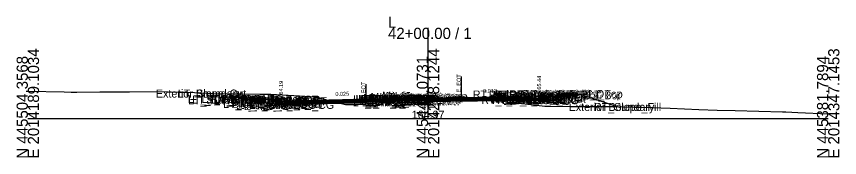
# Model space of a CAD drawing. Extents: x -26 to 4203, y -10 to 9526.
# Drawn here: x 2997.2 to 3202.8, y 1990.3 to 2025.4 of the extents above; entities that cross this region are included whole.
import ezdxf

# ---------------------------------------------------------------- set-up
doc = ezdxf.new("R2010")
doc.units = 0
for name, color, linetype in [('Default', 7, 'Continuous'), ('Exist CMT Pavement', 7, 'Continuous'), ('Exist Cross Section Cell', 7, 'Continuous'), ('Exist XS Center Line Elevation Label', 7, 'Continuous'), ('Exist XS Ground Line', 7, 'Continuous'), ('Prop CMT Conc Surface', 7, 'Continuous'), ('Prop CMT Concrete Structures', 7, 'Continuous'), ('Prop CMT Pvmt Course 1', 7, 'Continuous'), ('Prop CMT Pvmt Course 1 CG', 7, 'Continuous'), ('Prop CMT Pvmt Course 1 Wedge', 7, 'Continuous'), ('Prop CMT Pvmt Course 2', 7, 'Continuous'), ('Prop CMT Pvmt Course 2 Wedge', 7, 'Continuous'), ('Prop CMT Pvmt Course 3', 7, 'Continuous'), ('Prop CMT Pvmt Course 3 Wedge', 7, 'Continuous'), ('Prop CMT Pvmt Surface', 7, 'Continuous'), ('Prop CMT Pvmt Wedge Surface 1', 7, 'Continuous'), ('Prop CMT Pvmt Wedge Surface 2', 7, 'Continuous'), ('Prop CMT Pvmt Wedge Surface 3', 7, 'Continuous'), ('Prop CMT Slope Grass', 7, 'Continuous'), ('Prop CMT Subgrade Earthwork', 7, 'Continuous'), ('Prop XS Hydro Elevations', 7, 'Continuous'), ('Prop XS Label Text', 7, 'Continuous'), ('Prop XS SE Text', 7, 'Continuous'), ('Prop XS Side Slope Text', 7, 'Continuous'), ('Scratch_Level_0', 7, 'Continuous')]:
    doc.layers.add(name, color=color, linetype=linetype)

msp = doc.modelspace()

# ---------------------------------------------------------------- linework, layer by layer
at = {"layer": 'Exist CMT Pavement'}
for p, q in [((3084.46, 2003.6), (3085.63, 2003.74)), ((3085.63, 2003.74), (3089.14, 2004.08)), ((3089.14, 2004.08), (3092.69, 2004.41)), ((3092.69, 2004.41), (3095.44, 2004.64)), ((3095.44, 2004.64), (3096.5, 2004.72)), ((3096.5, 2004.72), (3099, 2004.9))]:
    msp.add_line(p, q, dxfattribs=at)
at = {"layer": 'Exist Cross Section Cell'}
for p, q in [((3100, 2000), (3100, 2022.62)), ((3000, 2000), (3100, 2000)), ((3100, 2000), (3200, 2000))]:
    msp.add_line(p, q, dxfattribs=at)
at = {"layer": 'Exist XS Ground Line'}
msp.add_lwpolyline([(3000, 2006.85), (3009.05, 2006.65), (3010.84, 2006.59), (3012.24, 2006.59), (3017.97, 2006.67), (3025.37, 2006.69), (3032.23, 2006.75), (3037.55, 2006.58), (3039.36, 2006.54), (3041.69, 2006.46), (3046.48, 2006.26), (3050.21, 2006.19), (3053.61, 2006.18), (3058.01, 2006.07), (3060.74, 2006.06), (3065.05, 2005.8), (3072.07, 2005.42), (3074.35, 2004.79), (3079.36, 2003.49), (3082.03, 2003.51), (3084.46, 2003.6), (3084.8, 2003.64), (3085.16, 2003.68), (3085.63, 2003.74), (3086.24, 2003.79), (3088.57, 2004.02), (3089.14, 2004.08), (3091.01, 2004.25), (3092.69, 2004.41), (3095.44, 2004.64), (3096.5, 2004.72), (3097.39, 2004.78), (3098.56, 2004.86), (3100, 2004.97), (3100.8, 2005.03), (3101.34, 2005.07), (3101.76, 2005.1), (3104.45, 2005.27), (3104.95, 2005.3), (3107.62, 2005.47), (3107.92, 2005.48), (3108.29, 2005.48), (3111.48, 2005.18), (3116.23, 2004.6), (3120.8, 2004.08), (3129.21, 2003.1), (3136.32, 2003.04), (3146.28, 2002.98), (3151.46, 2002.88), (3153.41, 2002.82), (3155.92, 2002.74), (3160.54, 2002.6), (3164.11, 2002.4), (3167.66, 2002.23), (3172.24, 2002.13), (3176.77, 2002.01), (3188.56, 2001.68), (3189.43, 2001.66), (3192.41, 2001.52), (3200, 2001.18)], dxfattribs=at)
at = {"layer": 'Prop CMT Conc Surface'}
for points in [[(3125.77, 2005.5), (3127.77, 2005.44)], [(3127.77, 2005.44), (3127.77, 2005.94), (3128.27, 2005.94)], [(3132.27, 2006.03), (3137.27, 2006.13)], [(3058.75, 2004.78), (3053.75, 2004.88)], [(3063.25, 2004.19), (3063.25, 2004.69), (3062.75, 2004.69)], [(3065.25, 2004.32), (3063.25, 2004.19)]]:
    msp.add_lwpolyline(points, dxfattribs=at)
at = {"layer": 'Prop CMT Concrete Structures'}
for points in [[(3099, 2005.18), (3098.99, 2005.35), (3098.24, 2005.6), (3095.5, 2005.65), (3092.76, 2005.41), (3092.01, 2005.16), (3092, 2004.99)], [(3125.77, 2005.5), (3127.77, 2005.44), (3127.77, 2005.94), (3128.27, 2005.94)], [(3128.27, 2005.94), (3128.27, 2004.94), (3125.77, 2004.91)], [(3125.77, 2004.91), (3125.77, 2005.5)], [(3137.27, 2006.13), (3132.27, 2006.03)], [(3132.27, 2006.03), (3132.27, 2005.7)], [(3132.27, 2005.7), (3137.27, 2005.8)], [(3137.27, 2005.8), (3137.27, 2006.13)], [(3053.75, 2004.55), (3053.75, 2004.88)], [(3053.75, 2004.88), (3058.75, 2004.78)], [(3058.75, 2004.45), (3053.75, 2004.55)], [(3058.75, 2004.78), (3058.75, 2004.45)], [(3065.25, 2004.32), (3063.25, 2004.19), (3063.25, 2004.69), (3062.75, 2004.69)], [(3062.75, 2004.69), (3062.75, 2003.68), (3065.25, 2003.74)], [(3065.25, 2003.74), (3065.25, 2004.32)], [(3092, 2004.99), (3099, 2005.18)]]:
    msp.add_lwpolyline(points, dxfattribs=at)
at = {"layer": 'Prop CMT Pvmt Course 1'}
for points in [[(3099, 2005.18), (3125.77, 2005.5)], [(3125.77, 2005.5), (3125.77, 2005.25)], [(3092, 2004.99), (3065.25, 2004.32)], [(3065.25, 2004.07), (3084.46, 2004.56)], [(3065.25, 2004.32), (3065.25, 2004.07)], [(3084.46, 2004.68), (3092, 2004.87)], [(3084.46, 2004.56), (3084.46, 2004.68)], [(3092, 2004.99), (3099, 2005.18)], [(3092, 2004.74), (3092, 2004.99)], [(3092, 2004.74), (3092, 2004.99)], [(3099, 2004.93), (3092, 2004.74)], [(3092, 2004.87), (3092, 2004.74), (3092, 2004.74)], [(3125.77, 2005.25), (3099, 2004.93)], [(3099, 2005.18), (3099, 2004.93)], [(3099, 2004.93), (3099, 2005.18)]]:
    msp.add_lwpolyline(points, dxfattribs=at)
msp.add_lwpolyline([(3099, 2004.93), (3099, 2005.06), (3099, 2005.06), (3099, 2004.93)], close=True, dxfattribs=at)
at = {"layer": 'Prop CMT Pvmt Course 1 CG'}
for points in [[(3065.25, 2003.74), (3062.25, 2003.67), (3061.91, 2003.32)], [(3061.91, 2003.32), (3065.25, 2003.41)], [(3065.25, 2003.41), (3065.25, 2003.74)], [(3125.77, 2004.91), (3128.77, 2004.95), (3129.1, 2004.62)], [(3125.77, 2004.58), (3125.77, 2004.91)], [(3129.1, 2004.62), (3125.77, 2004.58)]]:
    msp.add_lwpolyline(points, dxfattribs=at)
at = {"layer": 'Prop CMT Pvmt Course 1 Wedge'}
for points in [[(3084.46, 2004.68), (3084.8, 2004.69), (3085.16, 2004.7), (3085.52, 2004.71), (3085.63, 2004.71), (3086.24, 2004.72), (3088.57, 2004.78), (3089.14, 2004.8), (3091.01, 2004.84), (3092, 2004.87)], [(3092, 2004.74), (3091.01, 2004.72), (3089.14, 2004.67), (3088.57, 2004.66), (3086.24, 2004.6), (3085.63, 2004.58), (3085.52, 2004.58), (3085.16, 2004.57), (3084.8, 2004.56), (3084.46, 2004.56)], [(3084.46, 2004.56), (3084.46, 2004.68)], [(3092, 2004.87), (3092, 2004.74)]]:
    msp.add_lwpolyline(points, dxfattribs=at)
at = {"layer": 'Prop CMT Pvmt Course 2'}
for points in [[(3084.46, 2004.56), (3065.25, 2004.07)], [(3065.25, 2003.74), (3084.46, 2004.22)], [(3065.25, 2004.07), (3065.25, 2003.74)], [(3084.46, 2004.22), (3084.46, 2004.56)], [(3092, 2004.74), (3099, 2004.93)], [(3092, 2004.41), (3092, 2004.74)], [(3099, 2004.6), (3092, 2004.41)], [(3099, 2004.93), (3125.77, 2005.25)], [(3099, 2004.93), (3099, 2004.6)], [(3099, 2004.6), (3099, 2004.93)], [(3125.77, 2004.92), (3099, 2004.6)], [(3125.77, 2005.25), (3125.77, 2004.91)]]:
    msp.add_lwpolyline(points, dxfattribs=at)
at = {"layer": 'Prop CMT Pvmt Course 2 Wedge'}
for points in [[(3084.46, 2004.56), (3084.8, 2004.56), (3085.16, 2004.57), (3085.52, 2004.58), (3085.63, 2004.58), (3086.24, 2004.6), (3088.57, 2004.66), (3089.14, 2004.67), (3091.01, 2004.72), (3092, 2004.74)], [(3084.46, 2004.22), (3084.46, 2004.56)], [(3092, 2004.41), (3091.01, 2004.38), (3089.14, 2004.34), (3088.57, 2004.32), (3086.24, 2004.27), (3085.63, 2004.25), (3085.52, 2004.25), (3085.16, 2004.24), (3084.8, 2004.23), (3084.46, 2004.22)], [(3092, 2004.74), (3092, 2004.41)]]:
    msp.add_lwpolyline(points, dxfattribs=at)
at = {"layer": 'Prop CMT Pvmt Course 3'}
for points in [[(3084.46, 2004.22), (3065.25, 2003.74)], [(3065.25, 2003.74), (3065.25, 2003.41)], [(3084.46, 2003.89), (3084.46, 2004.22)], [(3092, 2004.41), (3099, 2004.6)], [(3099, 2004.6), (3125.77, 2004.92)], [(3099, 2004.6), (3099, 2004.26)], [(3099, 2004.26), (3099, 2004.6)], [(3125.77, 2004.58), (3099, 2004.26)], [(3125.77, 2004.91), (3125.77, 2004.58)]]:
    msp.add_lwpolyline(points, dxfattribs=at)
at = {"layer": 'Prop CMT Pvmt Course 3 Wedge'}
for points in [[(3084.46, 2004.22), (3084.8, 2004.23), (3085.16, 2004.24), (3085.52, 2004.25), (3085.63, 2004.25), (3086.24, 2004.27), (3088.57, 2004.32), (3089.14, 2004.34), (3091.01, 2004.39), (3092, 2004.41)], [(3092, 2004.34), (3091.01, 2004.25), (3089.14, 2004.08), (3088.57, 2004.02), (3086.24, 2003.79), (3085.63, 2003.74), (3085.52, 2003.72), (3085.16, 2003.68), (3084.8, 2003.64), (3084.46, 2003.6)], [(3084.46, 2003.6), (3084.46, 2004.22)], [(3092, 2004.41), (3092, 2004.34)]]:
    msp.add_lwpolyline(points, dxfattribs=at)
at = {"layer": 'Prop CMT Pvmt Surface'}
for points in [[(3099, 2005.18), (3125.77, 2005.5)], [(3092, 2004.99), (3065.25, 2004.32)], [(3092, 2004.99), (3099, 2005.18)]]:
    msp.add_lwpolyline(points, dxfattribs=at)
at = {"layer": 'Prop CMT Pvmt Wedge Surface 1'}
for points in [[(3084.46, 2004.56), (3065.25, 2004.07)], [(3065.25, 2004.07), (3065.25, 2004.32)], [(3092, 2004.87), (3084.46, 2004.68)], [(3084.46, 2004.68), (3084.46, 2004.56)], [(3092, 2004.99), (3092, 2004.74), (3092, 2004.74), (3092, 2004.87)]]:
    msp.add_lwpolyline(points, dxfattribs=at)
at = {"layer": 'Prop CMT Pvmt Wedge Surface 2'}
for points in [[(3092, 2004.74), (3065.25, 2004.07)], [(3065.25, 2004.07), (3065.25, 2004.32)], [(3092, 2004.99), (3092, 2004.74)]]:
    msp.add_lwpolyline(points, dxfattribs=at)
at = {"layer": 'Prop CMT Pvmt Wedge Surface 3'}
for points in [[(3092, 2004.41), (3065.25, 2003.74)], [(3065.25, 2003.74), (3065.25, 2004.32)], [(3092, 2004.99), (3092, 2004.41)]]:
    msp.add_lwpolyline(points, dxfattribs=at)
at = {"layer": 'Prop CMT Slope Grass'}
for points in [[(3062.75, 2004.69), (3053.25, 2004.88), (3049.28, 2006.21)], [(3128.27, 2005.94), (3137.27, 2006.12)], [(3137.27, 2006.12), (3137.77, 2006.13), (3147.24, 2002.98)]]:
    msp.add_lwpolyline(points, dxfattribs=at)
at = {"layer": 'Prop CMT Subgrade Earthwork'}
msp.add_line((3099, 2004.26), (3099, 2004.9), dxfattribs=at)
for points in [[(3125.77, 2004.58), (3129.1, 2004.62), (3130.46, 2005.99)], [(3065.25, 2003.41), (3061.91, 2003.32), (3060.49, 2004.74)], [(3084.46, 2003.89), (3065.25, 2003.41)], [(3084.46, 2003.89), (3084.48, 2003.6)], [(3099, 2004.26), (3125.77, 2004.58)]]:
    msp.add_lwpolyline(points, dxfattribs=at)
at = {"layer": 'Prop XS Label Text'}
for p, q in [((3108.29, 2010.48), (3108.29, 2005.48)), ((3084.46, 2008.6), (3084.46, 2003.6))]:
    msp.add_line(p, q, dxfattribs=at)

# ---------------------------------------------------------------- texts
at = {"layer": 'Default'}
msp.add_text('-', height=0.0001, dxfattribs=at).set_placement((3000, 2000))
at = {"layer": 'Exist Cross Section Cell'}
for s, p in [('L', (3090, 2022.62)), ('42+00.00 / 1', (3090, 2019.82))]:
    msp.add_text(s, height=2.8, dxfattribs=at).set_placement(p)
for s, p in [('E 2014189.1034', (3002.8, 1990)), ('E 2014268.1244', (3102.8, 1990)), ('E 2014347.1453', (3202.8, 1990)), ('N 445504.3568', (3000, 1990)), ('N 445443.0731', (3100, 1990)), ('N 445381.7894', (3200, 1990))]:
    msp.add_text(s, height=2.8, rotation=90, dxfattribs=at).set_placement(p)
at = {"layer": 'Exist XS Center Line Elevation Label'}
msp.add_text('164.97', height=2, dxfattribs=at).set_placement((3095.94, 1999.97))
at = {"layer": 'Prop XS Hydro Elevations'}
for s, p in [('165.44', (3128.27, 2006.44)), ('164.19', (3063.75, 2005.19))]:
    msp.add_text(s, height=1, rotation=90, dxfattribs=at).set_placement(p)
at = {"layer": 'Prop XS Label Text'}
for p in [(3108.19, 2006.5), (3084.36, 2004.62)]:
    msp.add_text('E. EOT', height=1, rotation=90, dxfattribs=at).set_placement(p)
at = {"layer": 'Prop XS SE Text'}
for s, rotation, p in [('0.025', 1.4327, (3076.87, 2005.61)), ('0.012', 0.6805, (3113.77, 2006.36))]:
    msp.add_text(s, height=1, rotation=rotation, dxfattribs=at).set_placement(p)
at = {"layer": 'Prop XS Side Slope Text'}
for p in [(3051.59, 2006.07), (3141.53, 2005.47)]:
    msp.add_text('3:1', height=1, rotation=341.5651, dxfattribs=at).set_placement(p)
at = {"layer": 'Scratch_Level_0'}
for s, p in [('Exterior Boundary', (3032, 2005.23)), ('LT_Slope_Cut', (3037.49, 2005.23)), ('LT_SDWK_Out_Top', (3039.99, 2003.89)), ('LT_SDWK_Out_Bot', (3040.02, 2003.55)), ('LT_Sub_Trench_Out_DLT', (3041.06, 2003.74)), ('LT_CSLP_Pnt', (3043.42, 2003.89)), ('LT_SDWK_In_Top', (3046.61, 2003.79)), ('LT_SDWK_In_Bot', (3046.64, 2003.45)), ('LT_CG_Top_Face', (3050.51, 2003.7)), ('LT_CG_Top_BOC', (3051.03, 2003.7)), ('LT_PV2_OEEOP', (3081.31, 2003.75)), ('LT_PV3_OEEOP', (3081.31, 2003.41)), ('LT_PV1_OEEOP', (3081.87, 2003.87)), ('LT_PV2_IEEOP', (3081.95, 2003.75)), ('LT_PV1_IEEOP', (3082.52, 2003.87)), ('LT_PV2_PGL1', (3082.88, 2003.75)), ('LT_PV3_PGL1', (3082.88, 2003.41)), ('LT_PV2_PGL', (3083.21, 2003.75)), ('LT_PV1_PGL', (3083.78, 2004)), ('MI_Face In', (3083.9, 2004.16)), ('MI_Top In', (3085.61, 2004.41)), ('RT_Sub_OEEOP', (3088.17, 2003.29)), ('RT_PV2_OEEOP', (3088.26, 2003.96)), ('RT_PV3_OEEOP', (3088.26, 2003.62)), ('MI_Crown', (3088.57, 2004.68)), ('RT_PV1_OEEOP', (3088.83, 2004.08)), ('RT_PV2_IEEOP', (3088.91, 2003.96)), ('MI_Face Out', (3089.26, 2004.37)), ('MI_Top Out', (3089.47, 2004.62)), ('RT_PV1_IEEOP', (3089.47, 2004.08)), ('RT_PV2_PGL1', (3089.83, 2003.93)), ('RT_PV3_PGL1', (3089.83, 2003.6)), ('RT_PV2_PGL', (3090.17, 2003.96)), ('MI_Bot Out', (3090.26, 2004.21)), ('RT_PV1_PGL', (3090.73, 2004.21)), ('RT_Sub_Trench_Out_DLT', (3111.21, 2004.99)), ('RT_Sub_OEOT_CG', (3113.32, 2003.59)), ('RT_CG_Top_Face', (3115.21, 2004.95)), ('RT_CG1_Shelf_Out', (3115.5, 2003.96)), ('RT_CG_Bot_IE', (3115.87, 2003.92)), ('RT_Sub_OEOT', (3116.03, 2003.59)), ('RT_PV2_OEOT', (3116.13, 2004.25)), ('RT_PV3_OEOT', (3116.13, 2003.92)), ('RT_CG_Top_Gut', (3116.19, 2004.45)), ('RT_PV1_OEOT', (3116.69, 2004.5)), ('RT_CG_Top_BOC', (3116.74, 2004.95)), ('RT_CG_Bot_BOC', (3116.77, 2003.95)), ('RT_Sub_OEOP', (3119.39, 2003.63)), ('RT_SDWK_In_Top', (3120.31, 2005.04)), ('RT_SDWK_In_Bot', (3120.34, 2004.7)), ('RT_SDWK_Out_Top', (3123.69, 2005.14)), ('RT_SDWK_Out_Bot', (3123.72, 2004.8)), ('RT_Shld_O', (3130.04, 2005.13)), ('CSLP_Pnt', (3130.87, 2005.14)), ('LT_CG1_Shelf_Out', (3048.8, 2002.67)), ('LT_CG_Bot_BOC', (3051.07, 2002.68)), ('LT_CG_Top_Gut', (3051.49, 2003.2)), ('LT_Sub_OEOP', (3052.02, 2002.33)), ('LT_Sub_OEOT_CG', (3052.62, 2002.41)), ('LT_CG_Bot_IE', (3055.16, 2002.74)), ('LT_Sub_OEOT', (3055.33, 2002.41)), ('LT_PV2_OEOT', (3055.42, 2003.08)), ('LT_PV3_OEOT', (3055.42, 2002.74)), ('LT_PV1_OEOT', (3055.99, 2003.33)), ('LT_Sub_OEEOP', (3081.21, 2003.08)), ('LT_PV4_PGL', (3083.21, 2003.08)), ('RT_PV4_PGL', (3090.17, 2003.27)), ('Exterior Boundary', (3135.15, 2001.89)), ('RT_Slope_Fill', (3141.48, 2001.89))]:
    msp.add_text(s, height=2, dxfattribs=at).set_placement(p)

doc.saveas('drawing.dxf')
